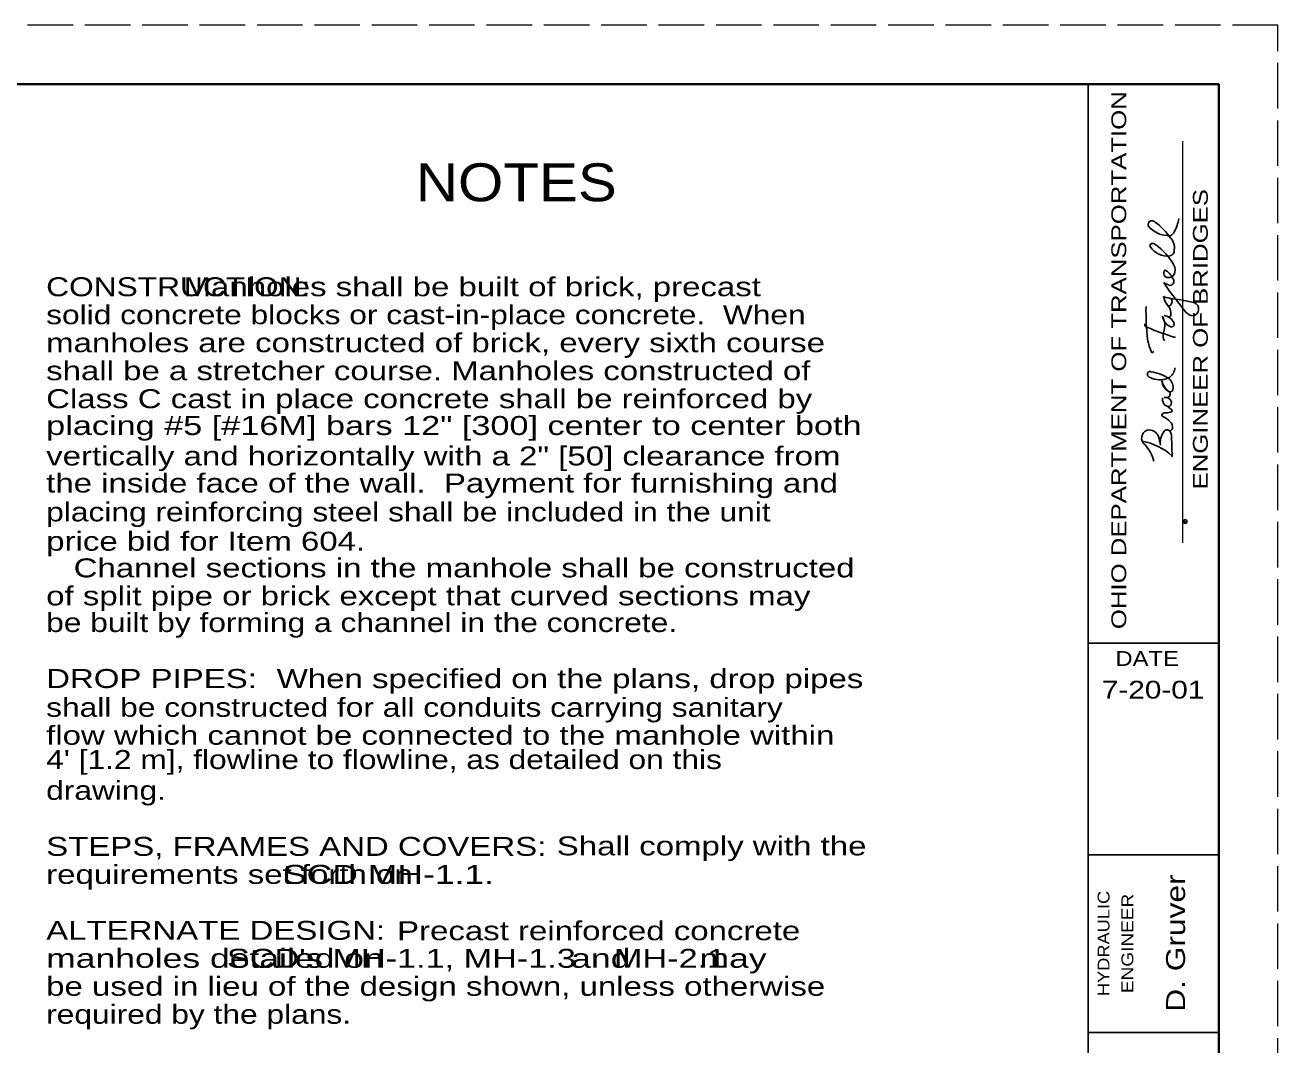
# Model space of a CAD drawing. Extents: x 750.7 to 784.7, y 860.1 to 882.1.
# Drawn here: x 774.08 to 784.65, y 873.51 to 882.12 of the extents above; entities that cross this region are included whole.
import ezdxf
from ezdxf.enums import TextEntityAlignment as Align

# ---------------------------------------------------------------- set-up
doc = ezdxf.new("R2010")
doc.units = 0
doc.header["$LTSCALE"] = 0.064
doc.header["$PDMODE"] = 32
doc.header["$PDSIZE"] = 0.032
doc.linetypes.add('LONG_DASHED', pattern=[7.5, 6, -1.5])
doc.layers.add('1', color=7, linetype='Continuous', lineweight=13)
doc.layers.add('43', color=7, linetype='Continuous', lineweight=25)
doc.layers.add('42', color=7, linetype='Continuous')

msp = doc.modelspace()

# ---------------------------------------------------------------- linework, layer by layer
at = {"layer": '1', "lineweight": 25}
for p, q in [((752.65083, 881.61842), (784.15083, 881.61842)), ((783.05083, 860.61842), (783.05083, 881.61842)), ((784.15083, 881.61842), (784.15083, 860.61842)), ((784.15083, 876.90258), (783.05083, 876.90258)), ((784.15083, 875.11842), (783.05083, 875.11842)), ((784.15083, 873.61842), (783.05083, 873.61842))]:
    msp.add_line(p, q, dxfattribs=at)
at = {"layer": '1'}
msp.add_line((783.84958, 877.74942), (783.84958, 881.1395), dxfattribs=at)
at = {"layer": '1', "linetype": 'LONG_DASHED'}
msp.add_lwpolyline([(750.65083, 860.11842), (784.65083, 860.11842), (784.65083, 882.11842), (750.65083, 882.11842)], close=True, dxfattribs=at)
at = {"layer": '1', "lineweight": 40}
msp.add_lwpolyline([(752.65083, 881.61842), (784.15083, 881.61842), (784.15083, 860.61842), (752.65083, 860.61842)], close=True, dxfattribs=at)
at = {"layer": '42'}
msp.add_point((783.86808, 877.92958), dxfattribs=at)
at = {"layer": '43'}
for p, q in [((783.68992, 879.458), (783.69808, 879.46083)), ((783.75417, 878.65425), (783.75742, 878.476))]:
    msp.add_line(p, q, dxfattribs=at)
for centre, radius, start, end in [((783.52, 880.52332), 0.29609, 329.12441, 352.69329), ((783.58806, 880.43505), 0.0333, 113.98019, 198.40352), ((783.72966, 880.56219), 0.22123, 218.47768, 273.26047), ((783.58539, 880.42478), 0.04212, 45.85596, 104.94474), ((783.29442, 880.01003), 0.54827, 34.63262, 54.25344), ((783.72648, 880.38998), 0.05116, 287.93982, 338.66307), ((783.59526, 880.25744), 0.02249, 124.49102, 212.28704), ((783.58946, 880.23695), 0.03963, 48.28094, 100.06036), ((783.33025, 879.84872), 0.50608, 29.47671, 55.64687), ((783.65785, 880.23974), 0.11998, 350.92499, 43.03504), ((783.71527, 880.33334), 0.16448, 212.30855, 277.889), ((783.73084, 880.21565), 0.04578, 278.80614, 6.47651), ((783.72539, 880.02508), 0.03785, 134.5839, 276.21021), ((783.70188, 880.05248), 0.08247, 328.86402, 33.28654), ((785.96566, 881.45725), 2.73372, 213.54695, 220.08659), ((783.80843, 880.12857), 0.21866, 236.35413, 252.38173), ((783.61743, 879.91157), 0.16234, 24.97701, 59.9081), ((783.72726, 880.04421), 0.0568, 272.24638, 322.76314), ((783.73662, 879.9564), 0.03666, 278.82355, 40.31415), ((785.67029, 879.70701), 2.13246, 179.00808, 186.45308), ((783.87403, 879.87126), 0.19335, 191.93662, 216.93201), ((783.83982, 880.34041), 0.53666, 253.73211, 261.66584), ((783.62706, 879.67714), 0.12119, 356.67266, 44.91278), ((783.73244, 879.76355), 0.01549, 213.1438, 334.3378), ((783.71106, 879.78686), 0.04637, 319.65709, 31.03704), ((783.4911, 877.82624), 2.00159, 76.85896, 82.22082), ((783.92351, 879.72131), 0.05865, 282.55689, 67.28157), ((783.4187, 879.54222), 0.28459, 13.60485, 24.73867), ((783.79938, 879.68304), 0.12413, 190.08126, 239.27146), ((783.67527, 879.56139), 0.10679, 31.60989, 82.17754), ((783.72845, 879.67737), 0.02089, 240.6235, 339.64142), ((783.94218, 879.75043), 0.08656, 218.20712, 266.08129), ((783.54704, 879.58894), 0.02035, 153.49478, 263.55592), ((784.69169, 882.3657), 3.02301, 247.70329, 252.57637), ((783.43492, 879.59157), 0.26098, 341.67711, 3.86341), ((783.75108, 879.59685), 0.02549, 233.58324, 53.58324), ((784.02867, 879.55255), 0.48488, 190.12054, 204.37157), ((783.7772, 879.49634), 0.09545, 172.05872, 203.71441), ((783.54639, 879.42768), 0.08548, 298.36136, 311.08751), ((783.66919, 879.23838), 0.11425, 301.08449, 348.26264), ((783.76356, 879.21865), 0.01785, 348.64966, 27.37763), ((783.57214, 879.17236), 0.02248, 69.75906, 198.23256), ((783.58784, 879.18101), 0.04023, 202.93968, 246.57643), ((783.52568, 878.82962), 0.36785, 55.75095, 81.52104), ((783.8278, 879.15553), 0.16087, 193.96867, 234.24124), ((783.7755, 879.12011), 0.10386, 181.88257, 246.32734), ((783.66329, 879.0578), 0.10284, 349.99119, 47.55407), ((783.71335, 879.00447), 0.02896, 269.53454, 45.09708), ((783.74314, 879.0449), 0.022, 244.8672, 346.93776), ((783.73719, 878.95848), 0.0605, 166.84439, 250.80516), ((783.70027, 878.92246), 0.05459, 59.10443, 99.26983), ((783.72546, 878.92559), 0.02565, 245.21977, 351.61479), ((783.33193, 878.33185), 0.68763, 52.41014, 55.91351), ((783.71007, 878.93158), 0.0419, 346.57725, 64.21305), ((783.69301, 878.82592), 0.02075, 98.82115, 193.06115), ((783.57279, 878.61286), 0.23113, 42.72148, 64.36086), ((783.70495, 878.98067), 0.13509, 263.57652, 288.13161), ((783.74418, 878.86541), 0.01341, 282.06688, 57.53058), ((783.5721, 878.63391), 0.07142, 110.48712, 231.46083), ((783.56347, 878.61743), 0.08498, 20.71835, 101.10772), ((783.8266, 878.59285), 0.16859, 144.2131, 186.6803), ((783.71398, 878.66942), 0.03268, 27.88325, 137.63831), ((783.73182, 878.72278), 0.02951, 278.12859, 343.88559), ((783.70551, 878.72748), 0.05617, 346.73401, 48.68598), ((783.67399, 878.64191), 0.08108, 8.73681, 31.85217), ((783.41739, 878.10792), 0.50704, 47.9273, 79.95075), ((783.30247, 878.36461), 0.31022, 13.62785, 43.47233), ((783.22107, 878.51524), 0.44213, 7.54019, 17.40463)]:
    msp.add_arc(centre, radius, start, end, dxfattribs=at)
msp.add_ellipse((783.65825, 879.32584), major_axis=(-0.08641, -0.18175), ratio=0.970189, start_param=6.28318531, end_param=7.10295967, dxfattribs=at)

# ---------------------------------------------------------------- texts
at = {"layer": '1'}
for s, height, width, p in [('OHIO DEPARTMENT OF TRANSPORTATION', 0.125, 1.3, (783.37075, 879.29067)), ('ENGINEER OF BRIDGES', 0.125, 1.3, (784.05908, 879.46746)), ('D. Gruver', 0.16, 1.25, (783.86725, 874.37258)), ('HYDRAULIC', 0.1, 1.15, (783.22992, 874.3695)), ('ENGINEER', 0.1, 1.2, (783.43083, 874.36954))]:
    msp.add_text(s, height=height, rotation=90, dxfattribs=dict(at, width=width)).set_placement(p, align=Align.CENTER)
for s, height, width, p in [('NOTES', 0.32, 1.15, (778.22621, 880.63142)), ('DATE', 0.125, 1.2, (783.54754, 876.71117)), ('7-20-01', 0.15, 1.25, (783.59787, 876.43567))]:
    msp.add_text(s, height=height, dxfattribs=dict(at, width=width)).set_placement(p, align=Align.CENTER)
for s, width, p in [('CONSTRUCTION: ', 1.25, (774.26017, 879.83025)), ('               Manholes shall be built of brick, precast', 1.3, (774.26017, 879.83025)), ('solid concrete blocks or cast-in-place concrete.  When', 1.25, (774.26017, 879.59417)), ('manholes are constructed of brick, every sixth course', 1.3, (774.26017, 879.35808)), ('shall be a stretcher course. Manholes constructed of', 1.3, (774.26017, 879.12192)), ('Class C cast in place concrete shall be reinforced by', 1.3, (774.26017, 878.88583)), ('placing #5 [#16M] bars 12" [300] center to center both', 1.35, (774.26017, 878.65942)), ('vertically and horizontally with a 2" [50] clearance from', 1.3, (774.2605, 878.40258)), ('the inside face of the wall.  Payment for furnishing and', 1.3, (774.2605, 878.17425)), ('placing reinforcing steel shall be included in the unit', 1.25, (774.2605, 877.93042)), ('price bid for Item 604.', 1.3, (774.26083, 877.68317)), ('   Channel sections in the manhole shall be constructed', 1.3, (774.2605, 877.45825)), ('of split pipe or brick except that curved sections may', 1.3, (774.2605, 877.22208)), ('be built by forming a channel in the concrete.', 1.25, (774.26017, 876.997)), ('DROP PIPES:', 1.3, (774.26017, 876.52483)), ('When specified on the plans, drop pipes', 1.3, (776.20517, 876.524)), ('shall be constructed for all conduits carrying sanitary', 1.25, (774.26017, 876.28167)), ('flow which cannot be connected to the manhole within', 1.3, (774.26017, 876.04558)), ("4' [1.2 m], flowline to flowline, as detailed on this", 1.25, (774.26017, 875.84117)), ('drawing.', 1.25, (774.26017, 875.58117)), ('STEPS, FRAMES AND COVERS:', 1.3, (774.26017, 875.10817)), (' Shall comply with the ', 1.3, (778.49, 875.11242)), ('requirements set forth on ', 1.3, (774.26017, 874.87208)), ('                        SCD MH-1.1.', 1.4, (774.26017, 874.87208)), ('ALTERNATE DESIGN:', 1.3, (774.26017, 874.4)), ('Precast reinforced concrete', 1.3, (777.22025, 874.3965)), ('manholes detailed on                   and       may', 1.4, (774.26017, 874.16392)), ("                   SCD's MH-1.1, MH-1.3    MH-2.1", 1.35, (774.26017, 874.16392)), ('be used in lieu of the design shown, unless otherwise', 1.3, (774.26017, 873.92783)), ('required by the plans.', 1.25, (774.26017, 873.69175))]:
    msp.add_text(s, height=0.16, dxfattribs=dict(at, width=width)).set_placement(p)

doc.saveas('drawing.dxf')
